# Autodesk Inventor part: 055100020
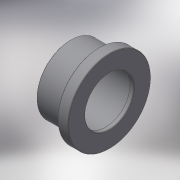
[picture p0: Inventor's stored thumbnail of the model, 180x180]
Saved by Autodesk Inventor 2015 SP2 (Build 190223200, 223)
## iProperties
Created: 2017-10
Part Number: 055100020
Material: Generic
Description: PLASSON FLANGE FLAT AD.-CEM 20
Document SubType Name: Modeling
Designer: KIM
Mass: 7.43257 g
Surface Area: 42.1155 cm^2
Volume: 7.43257 cm^3
Density: 1 g/cm^3
Appearance: Default
Author: KIM
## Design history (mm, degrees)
derived "055100.ipt"
feature "Solid1::055100.ipt"
tag "TaggingFeature1"
body "Solid1"
other parameters: "d0" = 19, "d1" = 27, "d3" = 18, "d4" = 7, "d5" = 16, "d6" = 34, "d8" = 0.2, "E_" = 27, "E_1" = 34, "l_" = 16, "B_" = 7, "H_" = 19
